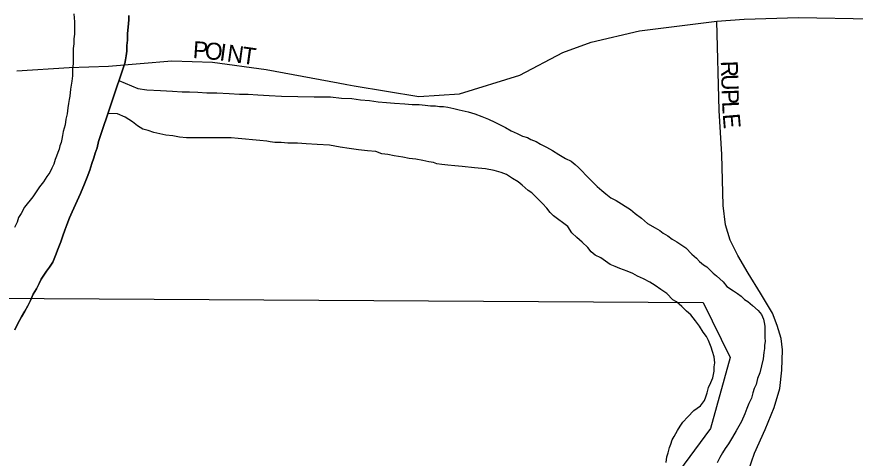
# Model space of a CAD drawing. Extents: x -561 to 1170, y 0 to 846.
# Drawn here: x 98.65 to 105.33, y 193.08 to 196.59 of the extents above; entities that cross this region are included whole.
import ezdxf

# ---------------------------------------------------------------- set-up
doc = ezdxf.new("R2010")
doc.units = 0
for name, color, linetype in [('GM_X_City_Street', 7, 'Continuous'), ('GM_X_City_Street_Text', 7, 'Continuous'), ('GM_X_Major_River', 7, 'Continuous'), ('GM_X_Township', 7, 'Continuous')]:
    doc.layers.add(name, color=color, linetype=linetype)

msp = doc.modelspace()

# ---------------------------------------------------------------- linework, layer by layer
at = {"layer": 'GM_X_City_Street'}
for points in [[(101.3405, 196.0461), (101.8544, 195.9602), (102.1784, 195.9821), (102.659, 196.1287), (103.0002, 196.3113), (103.2269, 196.3926), (103.6115, 196.4839), (104.2253, 196.5603)], [(104.2253, 196.5603), (104.4447, 196.5751), (104.876, 196.5899), (105.4577, 196.5776), (106.4948, 196.5894), (107.9896, 196.5564), (109.0886, 196.5344), (110.5493, 196.5472)], [(104.4784, 192.9812), (104.5254, 193.1194), (104.6119, 193.3091), (104.6841, 193.4845), (104.7273, 193.6362), (104.7447, 193.7802), (104.7487, 193.9441), (104.739, 194.0338), (104.7075, 194.1356), (104.6687, 194.235), (104.5742, 194.395), (104.4749, 194.5525), (104.3925, 194.6931), (104.3329, 194.8161), (104.2963, 194.9384), (104.2771, 195.091), (104.2663, 195.4969), (104.245, 195.8477), (104.2253, 196.5603)], [(98.6543, 196.1652), (99.0721, 196.1898), (99.3854, 196.201), (99.8877, 196.2449), (100.2119, 196.2343), (100.6386, 196.1753), (101.2113, 196.0677), (101.2812, 196.056), (101.3405, 196.0461)]]:
    msp.add_lwpolyline(points, dxfattribs=at)
at = {"layer": 'GM_X_Major_River'}
for points in [[(99.1072, 196.6184), (99.1129, 196.5534), (99.113, 196.4993), (99.1132, 196.4559), (99.1079, 196.418), (99.108, 196.38), (99.1027, 196.3421), (99.1028, 196.3096), (99.103, 196.2662), (99.1031, 196.2229), (99.0979, 196.1741), (99.0981, 196.1254), (99.0928, 196.082), (99.0875, 196.0495), (99.0822, 196.017), (99.0769, 195.9628), (99.0716, 195.9356), (99.0663, 195.9031), (99.061, 195.8706), (99.0558, 195.8218), (99.0451, 195.7784), (99.0398, 195.7351), (99.0237, 195.6809), (99.0184, 195.6483), (99.0131, 195.6212), (99.0078, 195.5941), (98.9971, 195.567), (98.9917, 195.5399), (98.981, 195.5128), (98.9702, 195.4856), (98.9595, 195.4585), (98.9488, 195.4205), (98.9327, 195.388), (98.9165, 195.3555), (98.8949, 195.3229), (98.868, 195.2794), (98.8356, 195.2414), (98.8033, 195.1925), (98.7817, 195.1599), (98.717, 195.0785), (98.6901, 195.0296), (98.6685, 194.9971), (98.6578, 194.9591), (98.6363, 194.9157)], [(99.1072, 196.6184), (99.1129, 196.5534), (99.113, 196.4993), (99.1132, 196.4559), (99.1079, 196.418), (99.108, 196.38), (99.1027, 196.3421), (99.1028, 196.3096), (99.103, 196.2662), (99.1031, 196.2229), (99.0979, 196.1741), (99.0981, 196.1254), (99.0928, 196.082), (99.0875, 196.0495), (99.0822, 196.017), (99.0769, 195.9628), (99.0716, 195.9356), (99.0663, 195.9031), (99.061, 195.8706), (99.0558, 195.8218), (99.0451, 195.7784), (99.0398, 195.7351), (99.0237, 195.6809), (99.0184, 195.6483), (99.0131, 195.6212), (99.0078, 195.5941), (98.9971, 195.567), (98.9917, 195.5399), (98.981, 195.5128), (98.9702, 195.4856), (98.9595, 195.4585), (98.9488, 195.4205), (98.9327, 195.388), (98.9165, 195.3555), (98.8949, 195.3229), (98.868, 195.2794), (98.8356, 195.2414), (98.8033, 195.1925), (98.7817, 195.1599), (98.717, 195.0785), (98.6901, 195.0296), (98.6685, 194.9971), (98.6578, 194.9591), (98.6363, 194.9157)], [(99.5461, 196.6036), (99.5462, 196.571), (99.541, 196.5114), (99.5358, 196.4626), (99.536, 196.4085), (99.5307, 196.3651), (99.5308, 196.3218), (99.5256, 196.2838), (99.5202, 196.2513), (99.5135, 196.2239)], [(99.5135, 196.2239), (99.5202, 196.2513), (99.5256, 196.2838), (99.5308, 196.3218), (99.5307, 196.3651), (99.536, 196.4085), (99.5358, 196.4626), (99.541, 196.5114), (99.5462, 196.571), (99.5461, 196.6036)], [(99.5135, 196.224), (99.3058, 195.6005), (99.2951, 195.5517), (99.279, 195.5083), (99.2683, 195.4703), (99.2522, 195.4269), (99.2361, 195.3727), (99.2146, 195.3185), (99.1931, 195.2642), (99.1609, 195.1883), (99.0964, 195.0418), (99.0749, 194.9929), (99.0534, 194.9387), (99.0373, 194.8953), (99.0212, 194.8519), (99.0051, 194.8031), (98.9836, 194.7488), (98.9621, 194.6946), (98.9407, 194.6403), (98.9137, 194.6023), (98.8921, 194.5698), (98.8706, 194.5372), (98.849, 194.5046), (98.8329, 194.472), (98.8113, 194.4286), (98.7844, 194.3852), (98.7629, 194.3364), (98.7414, 194.293), (98.7198, 194.2496), (98.6929, 194.2061), (98.6606, 194.1464), (98.6391, 194.103)], [(98.6391, 194.103), (98.6606, 194.1464), (98.6929, 194.2061), (98.7198, 194.2496), (98.7414, 194.293), (98.7629, 194.3364), (98.7844, 194.3852), (98.8113, 194.4286), (98.8329, 194.472), (98.849, 194.5046), (98.8706, 194.5372), (98.8921, 194.5698), (98.9137, 194.6023), (98.9407, 194.6403), (98.9621, 194.6946), (98.9836, 194.7488), (99.0051, 194.8031), (99.0212, 194.8519), (99.0373, 194.8953), (99.0534, 194.9387), (99.0749, 194.9929), (99.0964, 195.0418), (99.1609, 195.1883), (99.1931, 195.2642), (99.2146, 195.3185), (99.2361, 195.3727), (99.2522, 195.4269), (99.2683, 195.4703), (99.279, 195.5083), (99.2951, 195.5517), (99.3058, 195.6005), (99.5135, 196.224)], [(99.4679, 196.0871), (99.6185, 196.0241), (99.689, 196.0135), (99.7974, 196.0084), (99.8949, 196.0033), (99.9708, 195.9981), (100.0304, 195.9983), (100.0954, 195.9931), (100.1659, 195.9879), (100.2472, 195.9881), (100.3447, 195.983), (100.426, 195.9779), (100.4964, 195.9781), (100.5723, 195.9729), (100.6644, 195.9678), (100.7619, 195.9627), (101.022, 195.9581), (101.0816, 195.9583), (101.1521, 195.9585), (101.2388, 195.9479), (101.3201, 195.9428), (101.3905, 195.9321), (101.461, 195.927), (101.5315, 195.9164), (101.5965, 195.9111), (101.6615, 195.9059), (101.7428, 195.9007), (101.8024, 195.8955), (101.8566, 195.8957), (101.9054, 195.8904), (101.9487, 195.8851), (101.9867, 195.8853), (102.0192, 195.8799), (102.0517, 195.88), (102.0842, 195.8747), (102.133, 195.8641), (102.1764, 195.8533), (102.2469, 195.8373), (102.3011, 195.8212), (102.3554, 195.7997), (102.4096, 195.7782), (102.4585, 195.7567), (102.5019, 195.7352), (102.5453, 195.7137), (102.5887, 195.6867), (102.6376, 195.6652), (102.681, 195.6437), (102.719, 195.6329), (102.7461, 195.6168), (102.7895, 195.6006), (102.8221, 195.5791), (102.8709, 195.5575), (102.9198, 195.5306), (102.9686, 195.4983), (103.0229, 195.4659), (103.0664, 195.4444), (103.099, 195.4174), (103.1261, 195.3958), (103.1533, 195.3688), (103.1859, 195.331), (103.2349, 195.2824)], [(100.3621, 195.6309), (100.308, 195.6307), (100.2213, 195.6304), (100.1292, 195.6302), (100.0533, 195.6299), (100.0046, 195.6298), (99.9504, 195.635), (99.8962, 195.6457), (99.842, 195.6509), (99.7932, 195.6616), (99.7444, 195.6723), (99.7009, 195.6884), (99.6576, 195.6991), (99.6141, 195.7261), (99.5761, 195.7585), (99.5164, 195.7962), (99.4567, 195.8231), (99.3807, 195.8254)], [(103.8383, 193.1226), (103.8489, 193.1659), (103.8597, 193.193), (103.8704, 193.2256), (103.8866, 193.2527), (103.9135, 193.3016), (103.9351, 193.3342), (103.9566, 193.3667), (103.9944, 193.4102), (104.043, 193.4591), (104.097, 193.4972), (104.1294, 193.5406), (104.1402, 193.5678), (104.1508, 193.6003), (104.1615, 193.6437), (104.1777, 193.6816), (104.1938, 193.7196), (104.1991, 193.7467), (104.2044, 193.7738), (104.2043, 193.8064), (104.2096, 193.8389), (104.204, 193.8876), (104.193, 193.9309), (104.1821, 193.9634), (104.1602, 194.0175), (104.1439, 194.05), (104.1167, 194.0824), (104.0894, 194.1311), (104.0568, 194.1743), (104.0187, 194.2229), (103.9861, 194.2499), (103.948, 194.2877), (103.9046, 194.3255), (103.8774, 194.3417), (103.8285, 194.3903), (103.7796, 194.4227), (103.7361, 194.455), (103.6927, 194.482), (103.6439, 194.5089), (103.595, 194.5304), (103.557, 194.552), (103.5136, 194.5681), (103.4539, 194.5896), (103.416, 194.6057), (103.378, 194.6218), (103.34, 194.6488), (103.302, 194.6758), (103.2585, 194.6973), (103.226, 194.7243), (103.1987, 194.7567), (103.1552, 194.7999), (103.1118, 194.8378), (103.0737, 194.8756), (103.0411, 194.9242), (102.927, 195.0105), (102.8998, 195.0375), (102.8726, 195.07), (102.84, 195.1078), (102.8073, 195.1402), (102.7802, 195.1672), (102.753, 195.1942), (102.7258, 195.2104), (102.6769, 195.2535), (102.6443, 195.2805), (102.6009, 195.3075), (102.552, 195.3398), (102.5086, 195.356), (102.4544, 195.372), (102.3839, 195.3827), (102.2972, 195.3932), (102.1996, 195.4037), (102.14, 195.4089), (102.0858, 195.4142), (102.037, 195.4195), (101.9991, 195.4248), (101.972, 195.4355), (101.934, 195.4408), (101.8852, 195.4515), (101.831, 195.4622), (101.7768, 195.4674), (101.728, 195.4781), (101.6576, 195.4887), (101.6087, 195.4994), (101.56, 195.5047), (101.5112, 195.5208), (101.4461, 195.526), (101.3756, 195.5366), (101.2998, 195.5472), (101.2293, 195.5578), (101.1425, 195.5737), (101.045, 195.5789), (100.9583, 195.584), (100.8878, 195.5892), (100.812, 195.589), (100.7578, 195.5942), (100.709, 195.5941), (100.6711, 195.5994), (100.644, 195.6047), (100.5898, 195.61), (100.4164, 195.6256), (100.3621, 195.6309)], [(103.2349, 195.2824), (103.2729, 195.2446), (103.311, 195.2122), (103.3436, 195.1852), (103.3816, 195.1528), (103.425, 195.1313), (103.539, 195.0612), (103.5771, 195.0288), (103.626, 194.9911), (103.6749, 194.9479), (103.7346, 194.9156), (103.7726, 194.894), (103.7997, 194.8724), (103.8377, 194.8508), (103.8703, 194.8239), (103.9083, 194.8023), (103.9409, 194.7808), (103.979, 194.7538), (104.0279, 194.7052), (104.0659, 194.6728), (104.0877, 194.6458), (104.1203, 194.6188), (104.1474, 194.6026), (104.1963, 194.554), (104.2235, 194.5324), (104.2779, 194.4838), (104.3051, 194.446), (104.3594, 194.4136), (104.392, 194.3921), (104.4191, 194.3705), (104.4463, 194.3435), (104.4734, 194.3273), (104.5115, 194.2949), (104.5549, 194.2571), (104.5822, 194.2247), (104.5985, 194.1869), (104.6041, 194.1598), (104.6095, 194.1327), (104.6097, 194.0948), (104.6098, 194.0677), (104.6099, 194.0406), (104.61, 194.0081), (104.6047, 193.981), (104.6048, 193.9539), (104.5994, 193.9214), (104.5942, 193.8726), (104.5675, 193.7588), (104.5514, 193.7153), (104.5407, 193.6665), (104.5246, 193.634), (104.5139, 193.6014), (104.5032, 193.5581), (104.4816, 193.5147), (104.4655, 193.4767), (104.4494, 193.4333), (104.4225, 193.3736), (104.401, 193.3356), (104.3795, 193.2976), (104.3525, 193.2488), (104.3202, 193.1945), (104.2932, 193.1565), (104.2717, 193.1239), (104.2501, 193.0859), (104.2286, 193.0425)], [(103.8223, 193.0466), (103.8275, 193.09), (103.8383, 193.1226)]]:
    msp.add_lwpolyline(points, dxfattribs=at)
at = {"layer": 'GM_X_Township'}
msp.add_lwpolyline([(94.9365, 194.3754), (104.1165, 194.3195), (104.3326, 193.8807), (104.175, 193.3174), (103.7577, 192.7488), (102.9076, 192.5867), (102.1658, 192.5383), (101.2674, 192.815), (100.1737, 192.7505), (99.637, 191.9924), (98.9698, 190.5572), (99.3529, 189.2245), (99.9208, 188.6609), (100.809, 189.0234), (102.1142, 189.4507), (102.5844, 188.6975), (103.3043, 188.5239), (103.7484, 188.7187), (104.4903, 188.8483), (104.8469, 188.1548)], dxfattribs=at)

# ---------------------------------------------------------------- texts
at = {"layer": 'GM_X_City_Street_Text'}
for s, rotation, p in [('P', 355.78883, (100.0523, 196.2669)), ('O', 354.39597, (100.1462, 196.26)), ('I', 352.28405, (100.2632, 196.2486)), ('N', 352.12802, (100.3219, 196.2406)), ('T', 352.10749, (100.4396, 196.2243)), ('R', 271.77323, (104.2577, 196.2423)), ('U', 271.7708, (104.261, 196.1354)), ('P', 271.77829, (104.2647, 196.0167)), ('L', 272.98962, (104.2678, 195.9186)), ('E', 274.84099, (104.2731, 195.8191))]:
    msp.add_text(s, height=0.135, rotation=rotation, dxfattribs=at).set_placement(p)

doc.saveas('drawing.dxf')
